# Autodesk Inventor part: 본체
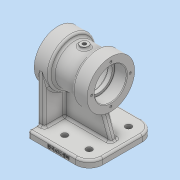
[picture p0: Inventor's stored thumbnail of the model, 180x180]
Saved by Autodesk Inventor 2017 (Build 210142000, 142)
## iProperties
Part Number: 본체
Material: 일반
Document SubType Name: Modeling
Designer: mrc
Density: 1 g/cm^3
Appearance: 기본값
Author: mrc
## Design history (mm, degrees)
sketch "스케치1"
  geometry: L1 (-39, 0)-(39, 0); L2 (-39, 0)-(-39, 35); L3 (-39, 35)-(-17, 35); L4 (-17, 35)-(-17, 29); L5 (-17, 29)-(17, 29); L6 (17, 29)-(17, 35); L7 (17, 35)-(39, 35); L8 (39, 35)-(39, 0); 2 further points
  constraints: 16 end point, 5 perpendicular, 2 midpoint, 2 point on line, 1 coincident, 1 horizontal, 1 vertical
  dimensions: "d0" = 78 distance of L1.start L1.end; "d1" = 70 diameter of L7 L1; "d2" = 58 diameter of L5 L1; "d3" = 22 distance of L6.end L7.end; "d4" = 22 distance of L2.end L3.end
revolve "회전1" sketch "스케치1" stored, may be unused: angle "d5" = 90 deg
sketch "스케치2"
  geometry: C1 r 23.5 at (0, 0); 1 further point
  constraints: 1 centre point, 1 coincident
  dimensions: "d6" = 47 diameter of C1
extrude "돌출1" cut sketch "스케치2" distance "d7" = 18; taper "d8" = 0 deg
sketch "스케치3"
  geometry: C1 r 20 at (0, 0); 1 further point
  constraints: 1 centre point, 1 coincident
  dimensions: "d9" = 40 diameter of C1
extrude "돌출2" cut sketch "스케치3" distance "d10" = 6; taper "d11" = 0 deg
sketch "스케치4"
  geometry: C1 r 23 at (0, 0); 1 further point
  constraints: 1 centre point, 1 coincident
  dimensions: "d12" = 46 diameter of C1
extrude "돌출3" cut sketch "스케치4" distance "d13" = 30; taper "d14" = 0 deg
node "작업 평면1"
sketch "스케치5"
  geometry: C1 r 6 at (0, 0); 1 further point
  constraints: 1 centre point, 1 coincident
  dimensions: "d16" = 12 diameter of C1
extrude "돌출4" join sketch "스케치5" stored distance "d17" = 30; taper "d18" = 0 deg
sketch "스케치6"
  geometry: C1 r 6 at (0, 0) reference; 2 further points
  constraints: 1 coincident
hole "구멍1" sketch "스케치6" at (0, 0) diameter "d19" = 5.188; stored, may be unused: countersink angle "d23" = 90 deg, drill point angle "d25" = 118 deg; dims "d20" = 12, "d21" = 4, "d22" = 2, "d24" = 16
sketch "스케치7" dims "d26" = 57
  geometry: 3 further points
  constraints: 2 vertical alignment, 1 coincident, 2 other
hole "구멍2" sketch "스케치7" at (0, 28.5) diameter "d27" = 3.242; stored, may be unused: countersink angle "d31" = 90 deg, drill point angle "d33" = 118 deg; dims "d28" = 10, "d29" = 4, "d30" = 2, "d32" = 12
node "작업 평면2"
sketch "스케치8"
  geometry: L1 (-34, -49)-(56, -49); L2 (56, -49)-(56, 49); L3 (56, 49)-(-34, 49); L4 (-34, 49)-(-34, -49); L5 (-34, -49)-(56, 49); L6 (56, -49)-(-34, 49); L7 (-39, -35)-(-39, 35) reference; 3 further points
  constraints: 12 end point, 3 midpoint, 2 parallel, 1 horizontal, 1 horizontal alignment, 1 perpendicular
  dimensions: "d38" = 90 distance of L3.end L2.end; "d39" = 98 distance of L1.end L2.end; "d40" = 5 distance between parallel lines of L7 L4
extrude "돌출5" join sketch "스케치8" distance "d41" = 10; taper "d42" = 0 deg
sketch "스케치9"
  geometry: L1 (-34, 49)-(-34, -49) reference; L2 (-34, -35)-(-34, 35); L3 (-34, 35)-(-24, 35); L4 (-24, 35)-(-24, -35); L5 (-24, -35)-(-34, -35); 3 further points
  constraints: 8 end point, 2 midpoint, 2 perpendicular, 2 point on line, 1 coincident
  dimensions: "d43" = 70 distance of L2.start L2.end; "d45" = 10 distance of L2.end L3.end; "d46" = 70 distance of L3.end L4.end
sketch "스케치10"
  geometry: L1 (-34, 49)-(-34, -49) reference; L2 (56, 49)-(-34, 49) reference; C1 r 4.5 at (36, 29); C2 r 4.5 at (0, 29); 1 further point
  constraints: 2 centre point
  dimensions: "d47" = 9 diameter of C1; "d48" = 9 diameter of C2; "d49" = 70 distance from line of L1 C1.centre; "d50" = 36 distance of C2.centre C1.centre; "d51" = 20 distance from line of L2 C1.centre; "d52" = 20 distance from line of L2 C2.centre
extrude "돌출6" cut sketch "스케치10" stored distance "d53" = 0; taper "d54" = 0 deg
fillet "모깎기1" dims "d55" = 20
fillet "모깎기2" dims "d56" = 3
extrude "돌출7" join sketch "스케치9" stored distance "d57" = 10; taper "d58" = 0 deg
sketch "스케치11"
  geometry: L1 (-56, -73)-(-56, -80) reference; L2 (-53, -70)-(-36, -70) reference; L3 (-44, -70)-(-31.261, -35); L4 (-17, -35)-(-39, -35) reference; 1 further point
  constraints: 2 end point, 2 point on line
  dimensions: "d60" = 12 distance from line of L1 L3.start; "d61" = 70 deg angle of L2 L3
feature "리브1" sketch "스케치11" dims "d62" = 1, "d63" = 10, "d64" = 0, "d65" = 0, "d66" = 1, "d67" = 1
sketch "스케치12"
  geometry: L1 (0, 0)-(70, 0) reference; L2 (0, 0)-(0, 7) reference; 2 further points
  constraints: 1 other
  dimensions: "d68" = 4 distance from line of L1 point (45, 4); "d69" = 45 distance from line of L2 point (45, 4)
feature "엠보싱1" sketch "스케치12" dims "d70" = 0.5, "d71" = 0
fillet "모깎기3" dims "d72" = 3
fillet "모깎기4" dims "d73" = 3
chamfer "모따기1" distance "d74" = 1; stored, may be unused: second distance "d75" = 2, angle "d76" = 45 deg
fillet "모깎기5" dims "d77" = 3
fillet "모깎기6" dims "d78" = 0.3
fillet "모깎기7" dims "d79" = 3
fillet "모깎기8" dims "d80" = 3
fillet "모깎기9" dims "d81" = 3
fillet "모깎기10" dims "d82" = 3
node "솔리드1"
mirror "미러1"
pattern_circular "원형 패턴1" dims angle "d35" = 360 deg
mirror "미러2"
mirror "미러3"
other parameters: "d15" = 32
